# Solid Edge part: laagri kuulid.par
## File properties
Author: KULL
Template: Iso Metric Part.par
Last saved by: KULL
Revision: 3
Application: Solid Edge
Accuracy: 0,990
Face Style: Model Default
Fill Style: Normal
Coef. of Thermal Exp: 0.0
Thermal Conductivity: 0.0
Specific Heat: 0.0
Modulus of Elasticity: 0.0
Poisson's Ratio: 0.0
Yield Stress: 0.0
Ultimate Stress: 0.0
Elongation: 0.0
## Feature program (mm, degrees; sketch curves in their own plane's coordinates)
pattern "unnamed Pattern 1"
Other named dimensions: "Pattern_2": XOffset = 45 deg
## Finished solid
Body 1: solid body, 8 faces, 0 edges, 0 vertices, 8 separate solids.
  Faces by surface: sphere 8
Spherical faces by radius (mm): R1.5 x8
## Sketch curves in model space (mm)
line (-10.4284, 0, 0) -> (16.1944, 0, 0)
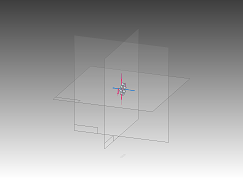
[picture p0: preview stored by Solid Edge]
